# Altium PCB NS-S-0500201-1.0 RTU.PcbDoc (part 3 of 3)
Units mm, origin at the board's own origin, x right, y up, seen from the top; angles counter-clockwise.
Board outline 170 x 90 mm, 6 copper layers (TOP, L2_GND, L3_SIG, L4_VCC, L5_GND, BOT), stack 1.4 mm thick; 260 components, 230 nets, 1133 pads, 705 vias.
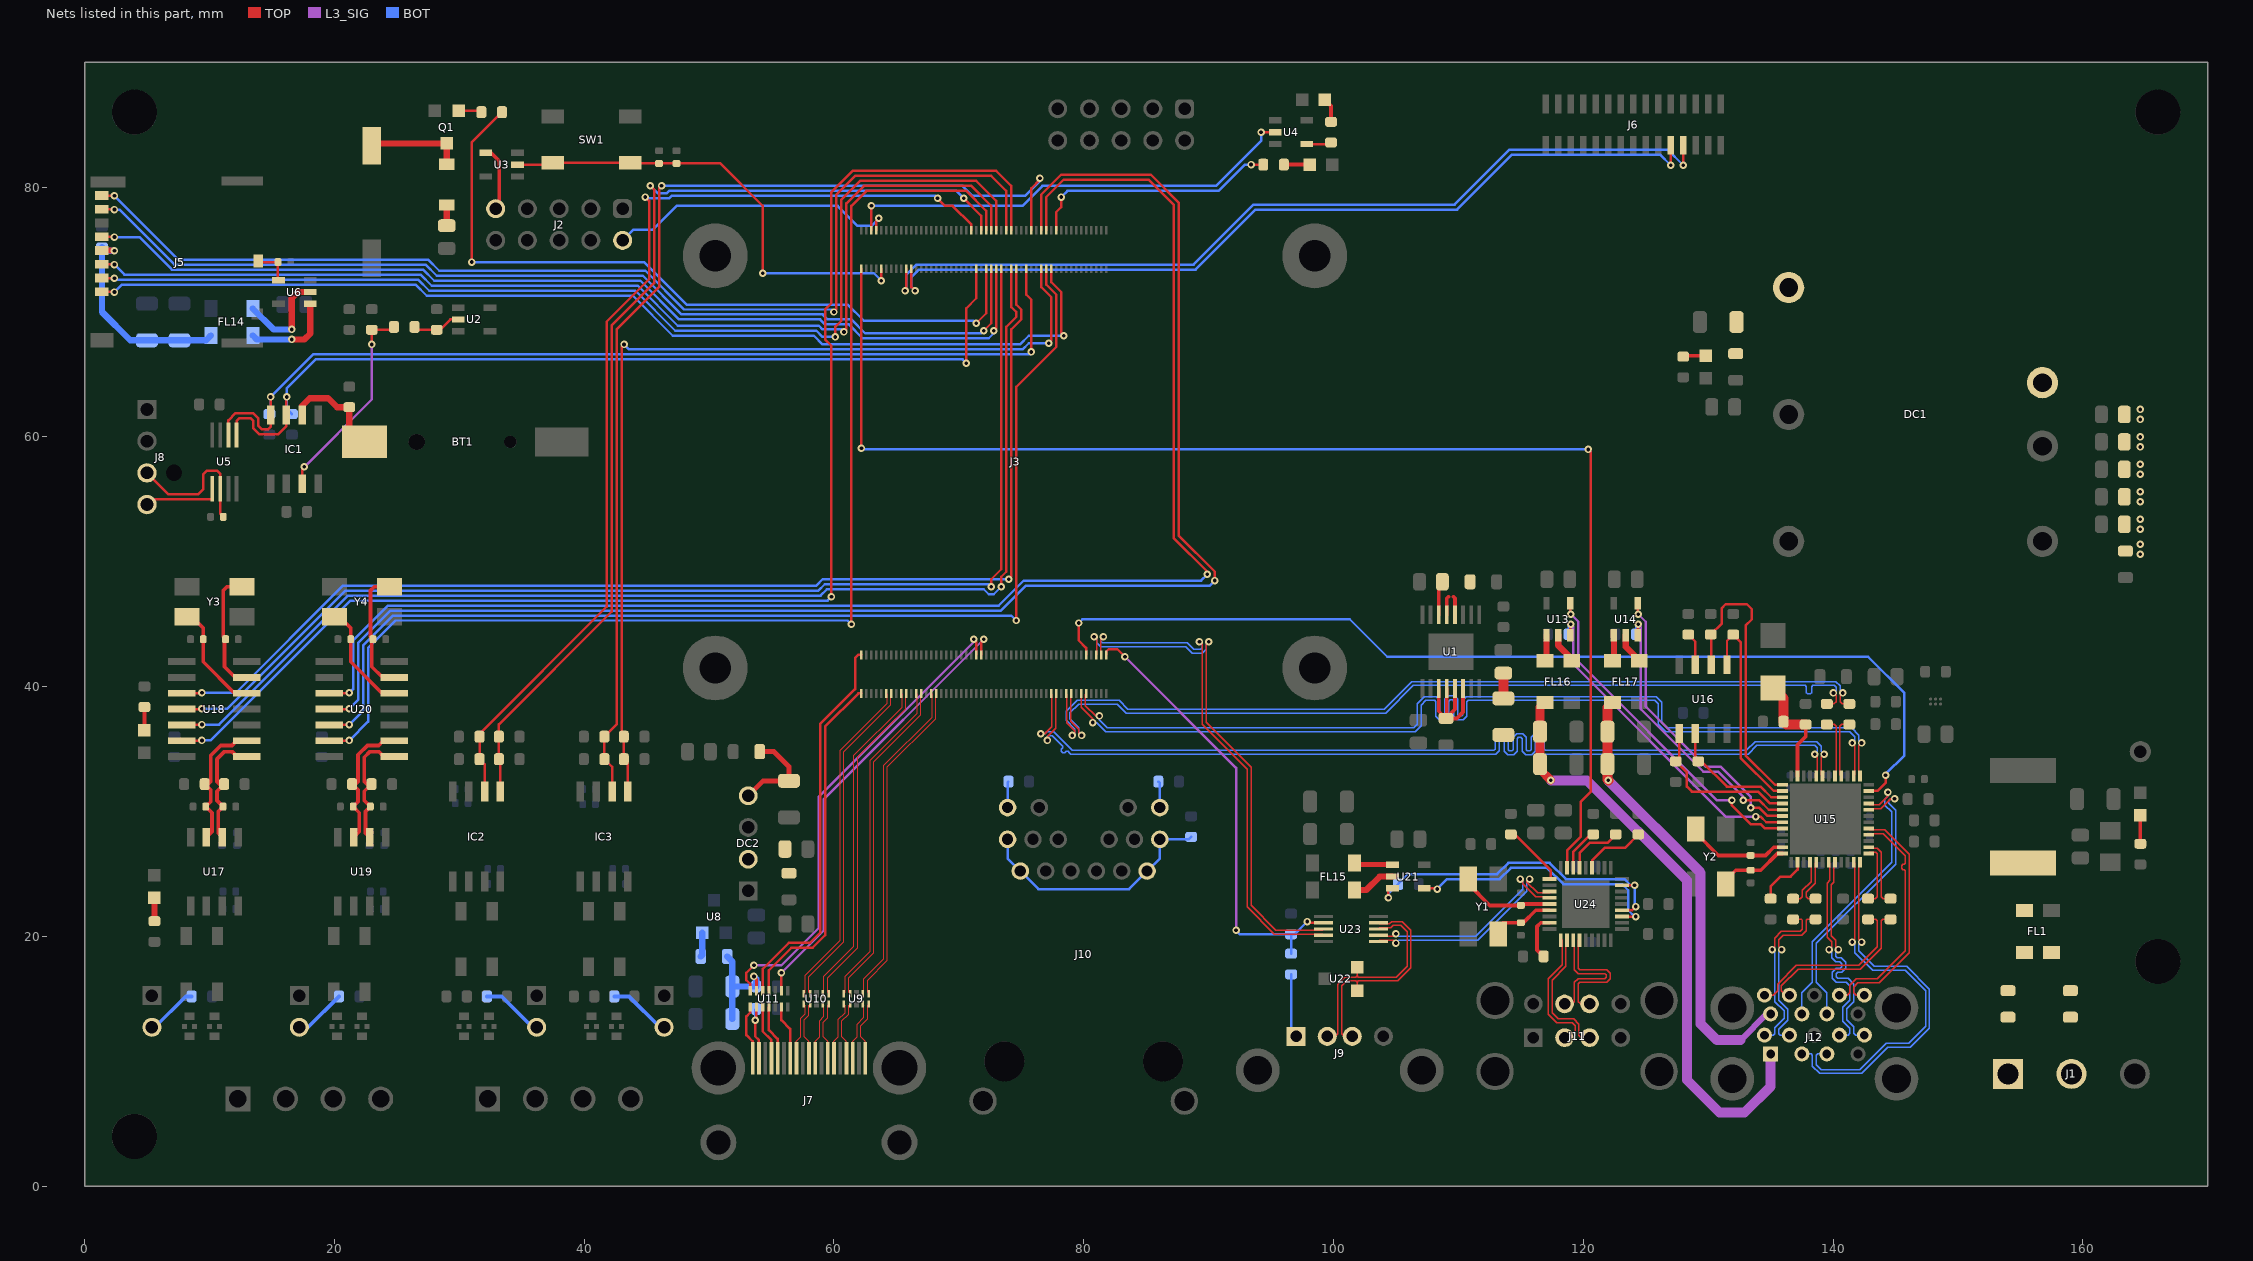
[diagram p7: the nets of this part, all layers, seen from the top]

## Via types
v1: diameter 0.6, hole 0.3, TOP to BOT, tented both sides, 705 vias

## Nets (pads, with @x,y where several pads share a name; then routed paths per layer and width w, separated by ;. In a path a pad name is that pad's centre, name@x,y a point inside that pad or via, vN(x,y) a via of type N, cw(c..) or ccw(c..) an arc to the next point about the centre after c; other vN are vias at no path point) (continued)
GPIO17: J3.50 R11.2 | length 60.1
  TOP w0.2: v1(31,74) 31,83.575 R11.2@33.425,86 ; v1(71.4,69.1) 72.2,69.9 J3.50@72.2,73.46
  BOT w0.2: v1(31,74) 44.8,74 48.2,70.6 61.1,70.6 62.4,69.3 71.2,69.3 v1(71.4,69.1)
HDMI0_CEC: J3.151 U11.9 | length 36.2
  TOP w0.2: U11.9@55.8,15.65 v1(55.8,17.1) ; J3.151@71.8,42.54 71.8,43.6 v1(72,43.8)
  L3_SIG w0.2: v1(55.8,17.1) 59.2,20.5 59.2,31 v1(72,43.8)
HDMI0_CLK1_N: J7.12 U10.1 | length 4.7
  TOP w0.09: J7.12@57,10.235 57,11.6 57.355,11.955 57.355,13.465 57.705,13.815 57.705,14.478 U10.1@57.6,14.583
HDMI0_CLK1_P: J7.10 U10.2 | length 4.7
  TOP w0.09: J7.10@58,10.235 58,11.6 57.645,11.955 57.645,13.345 57.995,13.695 57.995,14.478 U10.2@58.1,14.583
HDMI0_CLK_N: J3.190 U10.10 | length 26.8
  TOP w0.09: U10.10@57.6,15.417 57.705,15.522 57.705,16.915 60.5,19.71 60.5,34.9 64.255,38.655 64.255,39.405 J3.190@64.2,39.46
HDMI0_CLK_P: J3.188 U10.9 | length 26.8
  TOP w0.09: U10.9@58.1,15.417 57.995,15.522 57.995,16.795 60.79,19.59 60.79,34.78 64.545,38.535 64.545,39.405 J3.188@64.6,39.46
HDMI0_HOTPLUG: J3.153 U11.14 | length 38.4
  TOP w0.2: U11.14@53.3,15.65 53.3,16.2 53,16.5 53,17.1 v1(53.6,17.7) ; v1(71.2,43.8) 71.4,43.6 J3.153@71.4,42.54
  L3_SIG w0.2: v1(53.6,17.7) 55.8,17.7 58.8,20.7 58.8,31.2 71.2,43.6 v1(71.2,43.8)
HDMI0_SCL: J3.200 U11.11 | length 28
  TOP w0.2: U11.11@54.8,15.65 54.8,17.3 56.6,19.1 58.3,19.1 59.3,20.1 59.3,36.8 61.96,39.46 J3.200@62.2,39.46
HDMI0_SDA: J3.199 U11.12 | length 31.3
  TOP w0.2: U11.12@54.3,15.65 54.3,17.4 56.4,19.5 58.1,19.5 58.9,20.3 58.9,37 61.7,39.8 61.7,42.3 61.94,42.54 J3.199@62.2,42.54
HDMI0_TX0_N: J3.184 U10.7 | length 26.7
  TOP w0.09: U10.7@59.1,15.417 59.205,15.522 59.205,16.815 61.6,19.21 61.6,34.51 65.455,38.365 65.455,39.405 J3.184@65.4,39.46
HDMI0_TX0_P: J3.182 U10.6 | length 26.7
  TOP w0.09: U10.6@59.6,15.417 59.495,15.522 59.495,16.695 61.89,19.09 61.89,34.39 65.745,38.245 65.745,39.405 J3.182@65.8,39.46
HDMI0_TX01_N: J7.9 U10.4 | length 4.7
  TOP w0.09: J7.9@58.5,10.235 58.5,11.6 58.855,11.955 58.855,13.265 59.205,13.615 59.205,14.478 U10.4@59.1,14.583
HDMI0_TX1_N: J3.178 U9.10 | length 26.5
  TOP w0.09: U9.10@60.8,15.417 60.905,15.522 60.905,16.815 62.9,18.81 62.9,34.11 66.655,37.865 66.655,39.405 J3.178@66.6,39.46
HDMI0_TX01_P: J7.7 U10.5 | length 4.7
  TOP w0.09: J7.7@59.5,10.235 59.5,11.6 59.145,11.955 59.145,13.145 59.495,13.495 59.495,14.478 U10.5@59.6,14.583
HDMI0_TX1_P: J3.176 U9.9 | length 26.5
  TOP w0.09: U9.9@61.3,15.417 61.195,15.522 61.195,16.695 63.19,18.69 63.19,33.99 66.945,37.745 66.945,39.405 J3.176@67,39.46
HDMI0_TX2_N: J3.172 U9.7 | length 26.4
  TOP w0.09: U9.7@62.3,15.417 62.405,15.522 62.405,16.615 64,18.21 64,33.71 67.855,37.565 67.855,39.405 J3.172@67.8,39.46
HDMI0_TX2_P: J3.170 U9.6 | length 26.4
  TOP w0.09: U9.6@62.8,15.417 62.695,15.522 62.695,16.495 64.29,18.09 64.29,33.59 68.145,37.445 68.145,39.405 J3.170@68.2,39.46
HDMI0_TX11_N: J7.6 U9.1 | length 4.8
  TOP w0.09: J7.6@60,10.235 60,11.6 60.355,11.955 60.355,13.355 60.905,13.905 60.905,14.478 U9.1@60.8,14.583
HDMI0_TX11_P: J7.4 U9.2 | length 4.8
  TOP w0.09: J7.4@61,10.235 61,11.6 60.645,11.955 60.645,13.235 61.195,13.785 61.195,14.478 U9.2@61.3,14.583
HDMI0_TX21_N: J7.3 U9.4 | length 4.8
  TOP w0.09: J7.3@61.5,10.235 61.5,11.6 61.855,11.955 61.855,12.965 62.405,13.515 62.405,14.478 U9.4@62.3,14.583
HDMI0_TX21_P: J7.1 U9.5 | length 4.8
  TOP w0.09: J7.1@62.5,10.235 62.5,11.6 62.145,11.955 62.145,12.845 62.695,13.395 62.695,14.478 U9.5@62.8,14.583
HDMI_5V: C31.2 C32.2 C33.1 L12.2 U11.13 | length 9.2
  TOP w0.25: v1(53.6,16.8) 53.8,16.6 U11.13@53.8,15.65
  BOT w0.5: L12.2@51.463,18.4 51.865,17.997 C32.2@51.865,16 ; C31.2@51.865,13.4 C32.2@51.865,16 ; v1(53.6,16.8) 53.775,16.625 C33.1@53.775,16 C32.2@51.865,16
Net3V3_2: 3V3.2 R4.2 | length 1.9
  TOP w0.3: 3V3.2@4.8,36.5 R4.2@4.8,38.375
Net5V_2: 5V.2 R2.2 | length 1.8
  TOP w0.3: R2.2@128,66.425 128.075,66.5 5V.2@129.8,66.5
Net5V_ISO_2: 5V_ISO.2 R3.2 | length 1.9
  TOP w0.5: R3.2@5.6,21.225 5V_ISO.2@5.6,23.1
Net24V_2: 24V.2 R1.2 | length 2.3
  TOP w0.3: R1.2@164.6,27.425 24V.2@164.6,29.7
NetBT1_1: BT1.1 C21.1 IC1.6 | length 8.3
  TOP w0.5: IC1.6@17.435,61.75 17.435,62.5 18.035,63.1 19.5,63.1 20.225,62.375 C21.1@21.2,62.375 21.2,60.8 BT1.1@22.4,59.6
NetC1_1: C1.1 C2.1 C3.1 C4.1 C5.1 DC1.3 L1.2
  other v1: 164.6,50.6 164.6,51.4 164.6,52.6 164.6,53.4 164.6,54.8 164.6,55.6 164.6,57 164.6,57.8 164.6,59.2 164.6,60 164.6,61.4 164.6,62.2
NetC12_1: C12.1 L5.2 U1.12 U1.13 U1.14 | length 5.8
  TOP w0.3: U1.14@108.425,45.75 108.425,48.11 C12.1@108.715,48.4 ; U1.13@109.075,45.75 109.075,47.075 109.2,47.2 ; 109.6,47.2 109.725,47.075 U1.12@109.725,45.75
NetC14_1: C14.1 L6.1 U1.3 U1.4 U1.5 U1.6 | length 11.1
  TOP w0.3: U1.3@108.425,39.85 108.425,38.037 L6.1@109,37.462 ; U1.4@109.075,39.85 L6.1@109.075,37.537 ; U1.5@109.725,39.85 109.725,38.187 L6.1@109.075,37.537 ; U1.6@110.375,39.85 110.375,37.975 109.862,37.462 L6.1@109,37.462 ; L6.1@109,37.462 L6.1@109.075,37.537
NetC14_2: C14.2 R5.2 | length 2
  TOP w0.8: C14.2@113.6,39.065 R5.2@113.6,41.085
NetC15_1: C15.1 DC2.4 L8.1 | length 7.7
  TOP w0.4: DC2.4@53.14,31.27 54.335,32.465 C15.1@56.4,32.465 56.4,33.6 55.2,34.8 L8.1@54.063,34.8
NetC18_2: C18.2 DC2.2 L7.2
NetC23_2: C23.2 R13.1 U2.2 | length 3.9
  TOP w0.2: C23.2@26.425,68.8 26.65,68.575 R13.1@28.2,68.575 28.475,68.575 29.3,69.4 U2.2@29.93,69.4
NetC26_1: C26.1 DC1.4 L2.1
NetC34_1: C34.1 J7.18 U11.2 | length 5.2
  TOP w0.2: U11.2@53.8,14.35 53.8,13.4 v1(53.7,13.3) 53.7,12 54,11.7 J7.18@54,10.235
  BOT w0.2: v1(53.7,13.3) 53.7,14.125 C34.1@53.775,14.2
NetC43_1: C43.1 J10.1 J10.6 J10.7 J10.12 | length 19.9
  BOT w0.2: J10.12@73.905,27.78 73.905,26.26 J10.6@74.925,25.24 76.365,23.8 83.635,23.8 J10.1@85.075,25.24 86.095,26.26 J10.7@86.095,27.78 88.405,27.78 C43.1@88.6,27.975
NetC65_1: C65.1 U24.33 Y1.1 | length 5.2
  TOP w0.3: Y1.1@113.2,20.2 113.2,20.7 113.61,21.11 C65.1@115,21.11 115.21,21.11 116.2,22.1 U24.33@117.3,22.1
NetC66_1: C66.1 U24.32 Y1.3 | length 7.7
  TOP w0.3: Y1.3@110.8,24.6 110.8,24.2 112.51,22.49 C66.1@115,22.49 115.11,22.6 U24.32@117.3,22.6
NetC82_1: C82.1 D2.2 R30.2 U15.11 | length 9.3
  TOP w0.3: U15.11@137.15,32.85 137.15,35.35 137.8,36 R30.2@137.8,36.975
  TOP w0.8: D2.2@135.2,39.9 136.025,39.075 C82.1@136.025,37.2 136.25,36.975 R30.2@137.8,36.975
NetC85_1: C85.1 U15.24 Y2.1 | length 5.7
  TOP w0.3: Y2.1@131.4,24.2 131.4,24.5 132.21,25.31 C85.1@133.4,25.31 134.21,25.31 135.55,26.65 U15.24@135.95,26.65
NetC86_1: C86.1 U15.23 Y2.3 | length 8.3
  TOP w0.3: Y2.3@129,28.6 129,28.3 130.81,26.49 C86.1@133.4,26.49 134.59,26.49 135.25,27.15 U15.23@135.95,27.15
NetC93_1: C93.1 R38.2 U17.2 U18.1 | length 10.3
  TOP w0.3: U17.2@11.035,27.95 10.7,28.285 10.7,30.01 C93.1@11.09,30.4 10.6,30.89 10.6,31.625 R38.2@11.175,32.2 10.8,32.2 10.6,32.4 10.6,34.2 11.2,34.8 11.8,34.8 12.2,34.4 U18.1@13,34.4
NetC94_1: C94.1 R37.2 U17.3 U18.2 | length 11
  TOP w0.3: U17.3@9.765,27.95 10.2,28.385 10.2,29.91 C94.1@9.71,30.4 10.1,30.79 10.1,31.725 R37.2@9.625,32.2 9.9,32.2 10.1,32.4 10.1,34.5 10.9,35.3 11.8,35.3 12.17,35.67 U18.2@13,35.67
NetC95_1: C95.1 U18.6 Y3.1 | length 10
  TOP w0.3: Y3.1@12.6,48 11.4,48 11.1,47.7 11.1,43.99 C95.1@11.29,43.8 11.2,43.71 11.2,41.6 12.05,40.75 U18.6@13,40.75
NetC96_1: C96.1 U18.5 Y3.3 | length 8.9
  TOP w0.3: Y3.3@8.2,45.6 8.6,45.6 9.51,44.69 C96.1@9.51,43.8 9.51,41.99 12.02,39.48 U18.5@13,39.48
NetC98_1: C98.1 R41.2 U19.2 U20.1 | length 10.4
  TOP w0.3: U19.2@22.835,27.95 22.5,28.285 22.5,30.01 C98.1@22.89,30.4 22.4,30.89 22.4,31.625 R41.2@22.975,32.2 22.6,32.2 22.4,32.4 22.4,34.35 22.85,34.8 23.55,34.8 23.95,34.4 U20.1@24.8,34.4
NetC99_1: C99.1 R40.2 U19.3 U20.2 | length 11.1
  TOP w0.3: U19.3@21.565,27.95 22,28.385 22,29.91 C99.1@21.51,30.4 21.9,30.79 21.9,31.725 R40.2@21.425,32.2 21.7,32.2 21.9,32.4 21.9,34.55 22.65,35.3 23.55,35.3 23.92,35.67 U20.2@24.8,35.67
NetC100_1: C100.1 U20.6 Y4.1 | length 10
  TOP w0.3: Y4.1@24.4,48 23.2,48 22.9,47.7 22.9,43.99 C100.1@23.09,43.8 23,43.71 23,41.6 23.85,40.75 U20.6@24.8,40.75
NetC101_1: C101.1 U20.5 Y4.3 | length 8.9
  TOP w0.3: Y4.3@20,45.6 20.4,45.6 21.31,44.69 C101.1@21.31,43.8 21.31,41.99 23.82,39.48 U20.5@24.8,39.48
NetCPU_RUN_2: CPU_RUN.2 R14.2 | length 2.1
  TOP w0.3: R14.2@96.025,81.8 CPU_RUN.2@98.1,81.8
NetD1_1: D1.1 R7.1 | length 1.7
  TOP w0.5: R7.1@29,76.915 D1.1@29,78.565
NetD1_2: D1.2 LS1.N Q1.3 | length 7.7
  TOP w0.5: LS1.N@23,83.3 23.2,83.5 Q1.3@29,83.5 D1.2@29,81.835
NetFL1_1: FL1.1 L11.2
NetFL1_3: FL1.3 FUSE1.1
NetFL1_4: FL1.4 L10.2
NetFL14_2: FL14.2 U6.2 | length 8
  TOP w0.5: v1(16.6,68.6) 16.6,71.1 17.1,71.6 U6.2@18.07,71.6
  BOT w0.5: FL14.2@13.475,70.275 15.15,68.6 v1(16.6,68.6)
NetFL14_3: FL14.3 U6.1 | length 7.3
  TOP w0.5: v1(16.6,67.8) 17.6,67.8 18.07,68.27 U6.1@18.07,70.65
  BOT w0.5: FL14.3@13.475,68.125 13.8,67.8 v1(16.6,67.8)
NetFL15_1: FL15.1 U21.1 | length 3.1
  TOP w0.4: FL15.1@101.675,25.875 101.8,25.75 U21.1@104.73,25.75
NetFL15_4: FL15.4 U21.2 | length 3.5
  TOP w0.5: FL15.4@101.675,23.725 102.625,23.725 103.7,24.8 U21.2@104.73,24.8
NetFL16_1: FL16.1 U13.1 | length 2.1
  TOP w0.5: FL16.1@116.925,42.075 117.05,42.2 U13.1@117.05,44.13
NetFL16_4: FL16.4 U13.2 | length 2.5
  TOP w0.5: U13.2@118,44.13 118,43.3 119.075,42.225 FL16.4@119.075,42.075
NetFL17_1: FL17.1 U14.1 | length 2.1
  TOP w0.5: FL17.1@122.325,42.075 122.45,42.2 U14.1@122.45,44.13
NetFL17_4: FL17.4 U14.2 | length 2.5
  TOP w0.5: U14.2@123.4,44.13 123.4,43.2 124.475,42.125 FL17.4@124.475,42.075
NetJ1_1: J1.1 L10.1
NetJ1_2: J1.2 L11.1
NetJ2_9: J2.9 U3.4 | length 5.3
  TOP w0.3: U3.4@32.13,82.75 32.55,82.75 33.2,82.1 33.2,78.55 J2.9@32.92,78.27
NetJ5_10: J5.10 R17.2 U6.4 | length 3.1
  TOP w0.2: J5.10@13.915,74.095 14.01,74 R17.2@15.49,74 15.49,72.59 U6.4@15.53,72.55
NetJ7_13: J7.13 U11.6 | length 4.4
  TOP w0.2: U11.6@55.8,14.35 55.8,13.3 56.5,12.6 J7.13@56.5,10.235
NetJ7_15: J7.15 U11.4 | length 4.4
  TOP w0.2: U11.4@54.8,14.35 54.8,12.5 55.5,11.8 J7.15@55.5,10.235
NetJ7_16: J7.16 U11.3 | length 4.4
  TOP w0.2: U11.3@54.3,14.35 54.3,13.7 54.3,12.4 55,11.7 J7.16@55,10.235
NetJ7_19: J7.19 U11.1 | length 4.4
  TOP w0.2: U11.1@53.3,14.35 53.3,13.9 53,13.6 53,12.1 53.5,11.6 J7.19@53.5,10.235
NetJ8_3: J8.3 R16.1 U5.6 | length 11.7
  TOP w0.2: J8.3@5,57.12 6.72,55.4 9.1,55.4 9.5,55.8 9.5,57 9.8,57.3 10.6,57.3 10.875,57.025 U5.6@10.875,55.85 10.875,53.835 R16.1@11.11,53.6
NetJ8_4: J8.4 U5.5 | length 6.2
  TOP w0.2: J8.4@5,54.58 5.42,55 10.225,55 U5.5@10.225,55.85
NetJ9_1: J9.1 R54.2 | length 5.1
  BOT w0.2: R54.2@96.6,16.975 96.6,12.4 J9.1@97,12
NetJ10_13: J10.13 R21.1 | length 2.1
  BOT w0.2: R21.1@85.975,32.4 86.095,32.28 J10.13@86.095,30.32
NetJ10_16: J10.16 R22.1 | length 2.1
  BOT w0.2: J10.16@73.905,30.32 73.905,32.33 R22.1@73.975,32.4
NetJ14_2: J14.2 R39.1 | length 4.2
  BOT w0.3: J14.2@5.4,12.73 5.63,12.73 8.1,15.2 R39.1@8.575,15.2
NetJ15_2: J15.2 R42.1 | length 4.2
  BOT w0.3: J15.2@17.2,12.73 17.905,12.73 R42.1@20.375,15.2
NetJ17_2: J17.2 R47.1 | length 5
  BOT w0.3: R47.1@32.225,15.2 33.4,15.2 35.87,12.73 J17.2@36.2,12.73
NetJ18_2: J18.2 R52.1 | length 5
  BOT w0.3: R52.1@42.425,15.2 43.6,15.2 46.07,12.73 J18.2@46.4,12.73
NetL12_1: L12.1 U8.2 | length 1.9
  BOT w0.5: L12.1@49.338,18.4 49.45,18.512 U8.2@49.45,20.3
NetPWR_ON_2: PWR_ON.2 R15.2 | length 2
  TOP w0.3: PWR_ON.2@99.3,87 99.8,86.5 R15.2@99.8,85.225
NetQ1_1: Q1.1 R11.1 | length 1.9
  TOP w0.2: Q1.1@29.95,86.1 31.675,86.1 R11.1@31.775,86
NetR15_1: R15.1 U4.4 | length 2
  TOP w0.2: U4.4@97.87,83.45 99.675,83.45 R15.1@99.8,83.575
NetR31_2: R31.2 U15.26 | length 4.3
  TOP w0.2: R31.2@135,23.025 135,24 135.8,24.8 136.6,24.8 137.15,25.35 U15.26@137.15,25.95
NetR34_2: R34.2 U16.3 | length 2.7
  TOP w0.2: R34.2@128.4,44.175 128.965,43.61 U16.3@128.965,41.75
NetR56_2: R56.2 U24.24 | length 4.7
  TOP w0.2: U24.24@119.7,25.5 119.7,26.7 120.5,27.5 121.925,27.5 R56.2@122.6,28.175
NetR57_2: R57.2 U24.22 | length 5.2
  TOP w0.2: U24.22@120.7,25.5 120.7,26.1 121.7,27.1 123.325,27.1 R57.2@124.4,28.175
NetR58_2: R58.2 U24.28 | length 5.1
  TOP w0.2: R58.2@114.2,28.175 114.525,28.175 117.4,25.3 117.4,24.7 U24.28@117.3,24.6
NetR59_2: R59.2 U24.25 | length 3.5
  TOP w0.2: U24.25@119.2,25.5 119.2,26.8 120.575,28.175 R59.2@120.8,28.175
NetR60_2: R60.2 U24.35 | length 3.7
  TOP w0.3: R60.2@116.825,18.4 116.3,18.925 116.3,20.8 116.6,21.1 U24.35@117.3,21.1
nEXTRST: J3.100 U24.26 | length 107
  TOP w0.2: v1(62.2,59.1) J3.100@62.2,73.46 ; U24.26@118.7,25.5 118.7,26.9 119.8,28 119.8,30.8 120.6,31.6 120.6,58.8 v1(120.4,59)
  BOT w0.2: v1(62.2,59.1) 62.3,59 v1(120.4,59)
nRPIBOOT: J2.2 J3.93 | length 23.6
  TOP w0.2: J3.93@63.4,76.54 63.4,77.3 v1(63.6,77.5)
  BOT w0.2: J2.2@43.08,75.73 43.95,76.6 45.5,76.6 47.4,78.5 60.3,78.5 61.9,76.9 63,76.9 v1(63.6,77.5)
nRTC_INT: C23.1 IC1.3 R12.1 | length 16.5
  TOP w0.2: IC1.3@17.435,56.25 17.435,57.435 v1(17.6,57.6) ; v1(23,67.4) R12.1@23,68.575 24.55,68.575 C23.1@24.775,68.8
  L3_SIG w0.2: v1(17.6,57.6) 23,63 v1(23,67.4)
nUSB_OC: R53.2 U21.3 U24.13 U24.17 | length 26.9
  TOP w0.2: v1(104.4,23.1) 104.4,23.8 104.45,23.85 U21.3@104.73,23.85 ; U24.17@123,24.1 v1(124.1,24.1) ; U24.13@123.1,22.1 123.9,22.1 v1(124.2,22.4)
  BOT w0.2: v1(104.4,23.1) 104.4,23.425 105.975,25 113.1,25 114,25.9 117.3,25.9 118.6,24.6 123.3,24.6 123.8,24.1 v1(124.1,24.1) 124.1,22.5 v1(124.2,22.4)
OCI1B: R28.2 U13.3 U15.19 | length 27
  TOP w0.2: U13.3@118.95,44.13 118.95,44.95 v1(119,45) ; v1(133.8,29.6) 134.2,29.6 134.65,29.15 U15.19@135.95,29.15
  L3_SIG w0.2: v1(119,45) 119.2,44.8 119.2,41.8 131.4,29.6 v1(133.8,29.6)
  BOT w0.2: R28.2@118.825,44.2 118.825,44.825 v1(119,45)
OCI2B: R29.2 U14.3 U15.17 | length 23.5
  TOP w0.2: U14.3@124.35,44.13 124.35,44.95 v1(124.4,45) ; v1(132.8,30.9) 134.1,30.9 134.85,30.15 U15.17@135.95,30.15
  L3_SIG w0.2: v1(124.4,45) 124.6,44.8 124.6,38.2 129.6,33.2 130.8,33.2 132.8,31.2 v1(132.8,30.9)
  BOT w0.2: R29.2@124.225,44.2 124.225,44.825 v1(124.4,45)
PCIe_CLK_N: J3.112 U15.2 | length 76.9
  TOP w0.11: J3.112@79.8,39.46 79.8,38.362 80.725,37.436 v1(80.725,37.125) ; v1(141.525,35.5) 141.745,35.28 141.745,32.945 U15.2@141.65,32.85
  BOT w0.11: v1(80.725,37.125) 81.036,37.125 81.762,36.4 106.538,36.4 107.01,36.872 107.01,38.51 107.4,38.9 107.7,38.9 108.096,38.9 108.199,38.798 108.199,37.645 108.483,37.361 108.944,37.361 109.228,37.645 109.228,38.85 109.331,38.953 109.536,38.953 109.638,38.85 109.638,37.644 109.923,37.36 110.384,37.36 110.668,37.644 110.668,38.798 110.771,38.9 110.917,38.9 125.727,38.9 125.99,38.637 125.99,37.008 126.598,36.4 141.345,36.4 141.745,36 141.745,35.72 v1(141.525,35.5)
PCIe_CLK_P: J3.110 U15.1 | length 77
  TOP w0.11: J3.110@80.2,39.46 80.11,39.37 80.11,38.49 80.944,37.656 v1(81.256,37.656) ; U15.1@142.15,32.85 142.055,32.945 142.055,35.28 v1(142.275,35.5)
  BOT w0.11: v1(81.256,37.656) 81.256,37.344 81.89,36.71 106.41,36.71 106.7,37 106.7,38.638 107.272,39.21 107.7,39.21 108.224,39.21 108.509,38.926 108.509,37.774 108.611,37.671 108.816,37.671 108.918,37.774 108.918,38.979 109.203,39.263 109.664,39.263 109.948,38.979 109.948,37.773 110.051,37.67 110.256,37.67 110.358,37.773 110.358,38.926 110.643,39.21 110.917,39.21 125.855,39.21 126.3,38.765 126.3,37.137 126.727,36.71 141.473,36.71 142.055,36.128 142.055,35.72 v1(142.275,35.5)
PCIe_nRST: J3.109 U15.47 | length 80.9
  TOP w0.2: v1(79.6,45.1) 79.6,43.7 80.2,43.1 J3.109@80.2,42.54 ; U15.47@142.85,31.65 143.55,31.65 144.2,32.3 v1(144.2,32.9)
  BOT w0.2: v1(79.6,45.1) 79.9,45.4 101.3,45.4 104.3,42.4 142.8,42.4 145.7,39.5 145.7,34.5 144.2,33 v1(144.2,32.9)
PCIe_RX1_N: C78.2 U15.4 | length 4.8
  TOP w0.11: U15.4@140.65,32.85 140.55,32.95 140.55,36.845 140.68,36.975 C78.2@141.3,36.975
PCIe_RX1_P: C80.2 U15.5 | length 4.8
  TOP w0.11: C80.2@139.5,36.975 140.1,36.975 140.24,36.835 140.24,32.94 U15.5@140.15,32.85
PCIe_RX_N: C78.1 J3.118 | length 72
  TOP w0.11: J3.118@78.6,39.46 78.645,39.415 78.645,37.117 79.3,36.462 79.3,36.3 79.1,36.1 v1(79.08,36.1) ; v1(140.775,39.5) 140.555,39.28 140.555,38.8 140.73,38.625 C78.1@141.3,38.625
  BOT w0.11: v1(79.08,36.1) 79.3,36.32 79.3,36.6 78.59,37.31 78.59,38.028 79.472,38.91 82.828,38.91 83.538,38.2 104.062,38.2 106.272,40.41 140.228,40.41 140.555,40.083 140.555,39.72 v1(140.775,39.5)
PCIe_RX_P: C80.1 J3.116 | length 72.1
  TOP w0.11: J3.116@79,39.46 78.955,39.415 78.955,37.245 79.61,36.59 79.61,36.3 79.81,36.1 v1(79.83,36.1) ; C80.1@139.5,38.625 140.07,38.625 140.245,38.8 140.245,39.28 v1(140.025,39.5)
  BOT w0.11: v1(79.83,36.1) 79.61,36.32 79.61,36.728 78.9,37.438 78.9,37.9 79.6,38.6 82.7,38.6 83.41,37.89 104.19,37.89 106.4,40.1 137.3,40.1 137.765,40.1 137.868,39.998 137.868,39.52 137.97,39.418 138.175,39.418 138.278,39.52 138.278,39.998 138.38,40.1 138.5,40.1 140.1,40.1 140.245,39.955 140.245,39.72 v1(140.025,39.5)
PCIe_TX_N: J3.124 U15.7 | length 76.9
  TOP w0.11: v1(76.57,36.23) 76.881,36.23 77.445,36.795 77.445,39.415 J3.124@77.4,39.46 ; U15.7@139.15,32.85 139.055,32.945 139.055,34.38 v1(139.275,34.6)
  BOT w0.11: v1(76.57,36.23) 76.881,36.23 77.05,36.4 77.6,36.4 79.1,34.9 112.7,34.9 112.846,34.9 112.948,35.002 112.948,35.964 113.232,36.248 113.694,36.248 113.978,35.964 113.978,34.967 114.081,34.864 114.286,34.864 114.388,34.967 114.388,35.964 114.672,36.248 115.134,36.248 115.418,35.964 115.418,34.967 115.521,34.864 115.726,34.864 115.828,34.967 115.828,35.964 116.112,36.248 116.574,36.248 116.858,35.964 116.858,35.002 116.961,34.9 117.203,34.9 133.062,34.9 133.772,35.61 138.673,35.61 139.055,35.228 139.055,34.82 v1(139.275,34.6)
PCIe_TX_P: J3.122 U15.8 | length 76.9
  TOP w0.11: v1(77.1,35.7) 77.1,36.011 77.755,36.666 77.755,39.415 J3.122@77.8,39.46 ; v1(138.525,34.6) 138.745,34.38 138.745,32.945 U15.8@138.65,32.85
  BOT w0.11: v1(77.1,35.7) 77.1,36.011 77.179,36.09 77.472,36.09 77.981,35.58 78.02,35.542 78.31,35.252 78.31,35.107 78.187,34.984 78.187,34.839 78.332,34.694 78.477,34.694 78.6,34.817 78.745,34.817 78.832,34.729 78.871,34.69 78.972,34.59 112.7,34.59 112.974,34.59 113.258,34.874 113.258,35.836 113.361,35.938 113.566,35.938 113.668,35.836 113.668,34.838 113.952,34.554 114.414,34.554 114.698,34.838 114.698,35.836 114.801,35.938 115.006,35.938 115.108,35.836 115.108,34.838 115.392,34.554 115.854,34.554 116.138,34.838 116.138,35.836 116.241,35.938 116.446,35.938 116.548,35.836 116.548,34.874 116.832,34.59 117.203,34.59 133.19,34.59 133.9,35.3 138.545,35.3 138.745,35.1 138.745,34.82 v1(138.525,34.6)
PI_LED_nPWR: J3.95 U4.2 | length 37.1
  TOP w0.2: J3.95@63,76.54 v1(63,78.5) ; v1(94.2,84.4) U4.2@95.33,84.4
  BOT w0.2: v1(63,78.5) 75.1,78.5 76.7,80.1 90.6,80.1 94.2,83.7 v1(94.2,84.4)
Pi_nLED_Activity: J3.21 R14.1 | length 20.1
  TOP w0.2: J3.21@77.8,76.54 77.8,78 78.2,78.4 v1(78.2,79.2) ; v1(93.4,81.8) R14.1@94.375,81.8
  BOT w0.2: v1(78.2,79.2) 78.7,79.7 90.8,79.7 92.9,81.8 v1(93.4,81.8)
PPON1: U13.4 U15.20 | length 27.1
  TOP w0.2: U13.4@118.95,46.67 118.95,45.85 v1(119,45.8) ; v1(131.9,30.9) 131.9,30.5 133.4,29 134.2,29 134.55,28.65 U15.20@135.95,28.65
  L3_SIG w0.2: v1(119,45.8) 119.6,45.2 119.6,42 130.7,30.9 v1(131.9,30.9)
PPON2: U14.4 U15.18 | length 23.6
  TOP w0.2: U14.4@124.35,46.67 124.35,45.85 v1(124.4,45.8) ; v1(133.4,30.3) 134.1,30.3 134.75,29.65 U15.18@135.95,29.65
  L3_SIG w0.2: v1(124.4,45.8) 125,45.2 125,38.4 129.8,33.6 131,33.6 133.4,31.2 v1(133.4,30.3)
RUN_PG: C19.1 J3.92 R10.1 SW1.3 SW1.4 U3.2 | length 37.2
  TOP w0.2: U3.2@34.67,81.8 37.35,81.8 SW1.3@37.5,81.95 SW1.4@43.7,81.95 43.76,81.89 C19.1@46,81.89 R10.1@47.4,81.89 50.91,81.89 54.3,78.5 v1(54.3,73.1) ; v1(63.8,72.5) J3.92@63.8,73.46
  BOT w0.2: v1(54.3,73.1) 63.2,73.1 v1(63.8,72.5)
RXD0: C110.1 IC2.1 J3.51 R45.1 | length 82.6
  TOP w0.2: IC2.1@33.305,31.6 33.305,34.07 C110.1@33.175,34.2 R45.1@33.175,36 33.175,36.975 42.2,46 42.2,68.914 45.6,72.314 45.6,79.8 v1(45.3,80.1) ; v1(70.4,79.1) 71.8,77.7 J3.51@71.8,76.54
  BOT w0.2: v1(45.3,80.1) 45.9,79.5 46.6,79.5 46.8,79.7 69.8,79.7 v1(70.4,79.1)
RXD5: C116.1 IC3.1 J3.28 R50.1 | length 76.8
  TOP w0.2: v1(43.2,67.4) 43,67.2 43,36.175 R50.1@43.175,36 C116.1@43.175,34.2 43.505,33.87 IC3.1@43.505,31.6 ; J3.28@76.6,73.46 76.6,72 77.4,71.2 77.4,67.7 v1(77.2,67.5)
  BOT w0.2: v1(43.2,67.4) 43.6,67 75.1,67 75.6,67.5 v1(77.2,67.5)
SCL0: J3.80 J6.11 | length 69.9
  TOP w0.2: J3.80@66.2,73.46 66.2,72 v1(66.5,71.7) ; v1(127,81.75) J6.11@127,83.35
  BOT w0.2: v1(66.5,71.7) 66.2,72 66.2,72.8 66.8,73.4 88.966,73.4 93.766,78.2 109.9,78.2 114.3,82.6 126.15,82.6 v1(127,81.75)
SCL3: IC1.8 J3.34 R8.1 U5.2 | length 78.9
  TOP w0.2: U5.2@11.525,60.15 11.525,61.325 12.1,61.9 13.5,61.9 13.9,61.5 13.9,60.9 14.2,60.6 14.7,60.6 14.895,60.795 IC1.8@14.895,61.75 14.895,63.195 v1(14.9,63.2) ; J3.34@75.4,73.46 75.4,71.4 75.8,71 v1(75.8,66.8)
  BOT w0.2: R8.1@14.8,61.825 14.9,61.925 v1(14.9,63.2) 18.3,66.6 75.7,66.6 75.8,66.7 v1(75.8,66.8)
SD1_CLK: J3.46 J5.5 | length 80.2
  TOP w0.2: J5.5@1.375,76.02 2.38,76.02 v1(2.4,76) ; v1(72.8,68.5) 73,68.7 J3.46@73,73.46
  BOT w0.2: v1(2.4,76) 4.4,76 7,73.4 27.1,73.4 28,72.5 44.5,72.5 47.6,69.4 58.9,69.4 59.3,69 61.2,69 62.3,67.9 72.4,67.9 72.8,68.3 v1(72.8,68.5)
SD1_CMD: J3.47 J5.3 | length 86.9
  TOP w0.2: J5.3@1.375,73.82 2.38,73.82 v1(2.4,73.8) ; v1(60.8,68.4) 61,68.6 61,78.7 62.4,80.1 71,80.1 72.6,78.5 J3.47@72.6,76.54
  BOT w0.2: v1(2.4,73.8) 3.2,73 26.9,73 27.8,72.1 44.3,72.1 47.5,68.9 58.8,68.9 59.1,68.6 60.6,68.6 v1(60.8,68.4)
SD1_DAT0: J3.48 J5.7 | length 80
  TOP w0.2: J5.7@1.375,78.22 2.38,78.22 v1(2.4,78.2) ; v1(72,68.5) 72.6,69.1 J3.48@72.6,73.46
  BOT w0.2: v1(2.4,78.2) 2.8,78.2 7.2,73.8 27.3,73.8 28.2,72.9 44.7,72.9 47.8,69.8 59.1,69.8 59.5,69.4 61.4,69.4 62.5,68.3 71.8,68.3 v1(72,68.5)
SD1_DAT1: J3.41 J5.8 | length 89.8
  TOP w0.2: J5.8@1.375,79.32 2.38,79.32 v1(2.4,79.3) ; v1(60,70) 60.2,70.2 60.2,79.4 61.7,80.9 72.6,80.9 73.8,79.7 J3.41@73.8,76.54
  BOT w0.2: v1(2.4,79.3) 7.5,74.2 27.5,74.2 28.4,73.3 44.9,73.3 48,70.2 59.8,70.2 v1(60,70)
SD1_DAT2: J3.24 J5.1 | length 85.3
  TOP w0.2: J5.1@1.375,71.62 2.38,71.62 v1(2.4,71.6) ; J3.24@77.4,73.46 77.4,72.4 78.2,71.6 78.2,68.3 v1(78.4,68.1)
  BOT w0.2: v1(2.4,71.6) 3,72.2 26.5,72.2 27.4,71.3 43.9,71.3 47.1,68.1 58.4,68.1 59.1,67.4 74.9,67.4 75.6,68.1 v1(78.4,68.1)
SD1_DAT3: J3.45 J5.2 | length 88
  TOP w0.2: J5.2@1.375,72.72 2.38,72.72 v1(2.4,72.7) ; v1(60.1,68) 60.1,68.8 60.6,69.3 60.6,79 62.1,80.5 71.4,80.5 73,78.9 J3.45@73,76.54
  BOT w0.2: v1@2.429,72.7 v1(2.4,72.7) 2.5,72.6 26.7,72.6 27.6,71.7 44.1,71.7 47.3,68.5 58.6,68.5 59.1,68 v1(60.1,68)
SD_PWR: C24.1 C27.2 C28.2 FL14.4 J5.4 | length 17.1
  TOP w0.5: J5.4@1.375,74.92 2.38,74.92 v1(2.4,74.9)
  BOT w0.5: v1(2.4,74.9) 1.675,74.9 C24.1@1.4,75.175 1.4,70 3.665,67.735 C28.2@5,67.735 C27.2@7.6,67.735 9.735,67.735 FL14.4@10.125,68.125
SDA0: J3.82 J6.12 | length 71.6
  TOP w0.2: v1(65.7,71.7) 65.8,71.8 J3.82@65.8,73.46 ; v1(128,81.75) J6.12@128,83.35
  BOT w0.2: v1(65.7,71.7) 65.8,71.8 65.8,73 66.6,73.8 88.8,73.8 93.6,78.6 109.7,78.6 114.1,83 126.75,83 v1(128,81.75)
SDA3: IC1.7 J3.54 R9.1 U5.1 | length 74.3
  TOP w0.2: U5.1@12.175,60.15 12.175,61.275 12.4,61.5 13.3,61.5 13.5,61.3 13.5,60.7 14,60.2 15.5,60.2 16.165,60.865 IC1.7@16.165,61.75 16.165,63.165 v1(16.2,63.2) ; v1(70.6,65.9) 70.6,70.3 71.4,71.1 J3.54@71.4,73.46
  BOT w0.2: R9.1@16.6,61.825 16.2,62.225 v1(16.2,63.2) 16.2,63.9 18.5,66.2 70.3,66.2 v1(70.6,65.9)
SPI0_CE0_N: J3.39 U18.13 | length 108.8
  TOP w0.2: U18.13@7.8,35.67 9.37,35.67 v1(9.4,35.7) ; v1(59.8,47.2) 59.8,67.3 59.3,67.8 59.3,70.2 59.8,70.7 59.8,79.6 61.5,81.3 73,81.3 74.2,80.1 J3.39@74.2,76.54
  BOT w0.2: v1(9.4,35.7) 10.1,35.7 21.3,46.9 59.5,46.9 v1(59.8,47.2)
SPI0_MISO: J3.40 U18.12 | length 96.6
  TOP w0.2: U18.12@7.8,36.94 9.37,36.94 v1(9.4,36.97) ; v1(73.4,48) 73.4,48.8 73.8,49.2 73.8,68.8 74.6,69.6 74.6,70 74.2,70.4 J3.40@74.2,73.46
  BOT w0.2: v1(9.4,36.97) 10.77,36.97 21.1,47.3 58.931,47.3 59.431,47.8 72,47.8 72.4,47.4 72.8,47.4 v1(73.4,48)
SPI0_MOSI: J3.44 U18.11 | length 94.8
  TOP w0.2: U18.11@7.8,38.21 9.37,38.21 v1(9.4,38.24) ; v1(72.6,48) 72.6,48.6 73.4,49.4 J3.44@73.4,73.46
  BOT w0.2: v1(9.4,38.24) 11.44,38.24 20.9,47.7 58.766,47.7 59.266,48.2 72.4,48.2 v1(72.6,48)
SPI0_SCLK: J3.38 U18.10 | length 95.4
  TOP w0.2: U18.10@7.8,39.48 9.37,39.48 v1(9.4,39.51) ; v1(74,48.6) 74.2,48.8 74.2,68.6 75,69.4 75,70.2 74.6,70.6 J3.38@74.6,73.46
  BOT w0.2: v1(9.4,39.51) 12.11,39.51 20.7,48.1 58.6,48.1 59.1,48.6 v1(74,48.6)
SPI6_CE0_N: J3.49 U20.13 | length 96.4
  TOP w0.2: U20.13@19.6,35.67 21.17,35.67 v1(21.2,35.7) ; v1(61.4,45) 61.4,78.5 62.6,79.7 70.6,79.7 72.2,78.1 J3.49@72.2,76.54
  BOT w0.2: v1(21.2,35.7) 22.7,37.2 22.7,43.1 24.9,45.3 61.1,45.3 v1(61.4,45)
SPI6_MISO: J3.26 U20.12 | length 91.7
  TOP w0.2: U20.12@19.6,36.94 21.17,36.94 v1(21.2,36.97) ; v1(74.6,45.3) 74.6,64 77.8,67.2 77.8,71.4 77,72.2 J3.26@77,73.46
  BOT w0.2: v1(21.2,36.97) 22.3,38.07 22.3,43.3 24.7,45.7 74.2,45.7 v1(74.6,45.3)
SPI6_MOSI: J3.27 U20.11 | length 124.7
  TOP w0.2: U20.11@19.6,38.21 21.17,38.21 v1(21.2,38.24) ; J3.27@76.6,76.54 76.6,79.4 78.2,81 85.366,81 87.6,78.766 87.6,52.1 90.5,49.2 v1(90.5,48.5)
  BOT w0.2: v1(21.2,38.24) 21.9,38.94 21.9,43.5 24.5,46.1 73.366,46.1 75.366,48.1 90.1,48.1 v1(90.5,48.5)
SPI6_SCLK: J3.25 U20.10 | length 121.6
  TOP w0.2: U20.10@19.6,39.48 21.17,39.48 v1(21.2,39.51) ; J3.25@77,76.54 77,79.2 78.4,80.6 85.2,80.6 87.2,78.6 87.2,51.9 89.9,49.2 v1(89.9,49)
  L3_SIG w0.2: v1(89.9,49) v1@90,49
  BOT w0.2: v1(21.2,39.51) 21.5,39.81 21.5,43.7 24.3,46.5 73.2,46.5 75.2,48.5 89.4,48.5 v1(89.9,49)
SPICSB: R32.2 U15.14 U16.1 | length 17.2
  TOP w0.2: U16.1@131.505,41.75 131.505,43.68 R32.2@132,44.175 132.6,43.575 132.6,34.3 135.25,31.65 U15.14@135.95,31.65
SPISCK: R36.2 U15.15 U16.6 | length 10.3
  TOP w0.2: U16.6@128.965,36.25 128.965,34.26 R36.2@129.2,34.025 129.475,34.025 131.5,32 134.2,32 135.05,31.15 U15.15@135.95,31.15
SPISI: R35.2 U15.16 U16.5 | length 13
  TOP w0.2: U16.5@127.695,36.25 127.695,34.32 R35.2@127.4,34.025 128.3,33.125 128.3,32 128.7,31.6 134,31.6 134.95,30.65 U15.16@135.95,30.65
SPISO: R33.2 U15.13 U16.2 | length 23.5
  TOP w0.2: U16.2@130.235,41.75 130.235,44.14 R33.2@130.2,44.175 131.1,45.075 131.1,46.3 131.4,46.6 133.1,46.6 133.5,46.2 133.5,45.4 133,44.9 133,34.5 135.35,32.15 U15.13@135.95,32.15
TXD0: C111.1 IC2.2 J3.55 R44.2 | length 81.2
  TOP w0.2: IC2.2@32.035,31.6 32.035,33.79 C111.1@31.625,34.2 R44.2@31.625,36 31.625,36.225 41.8,46.4 41.8,69.221 45.2,72.621 45.2,78.9 v1(44.9,79.2) ; v1(68.3,79.1) 68.9,78.5 69.5,78.5 71,77 J3.55@71,76.54
  BOT w0.2: v1(44.9,79.2) 45,79.1 46.8,79.1 47,79.3 68.1,79.3 v1(68.3,79.1)
TXD5: C117.1 IC3.2 J3.31 R49.2 | length 86.4
  TOP w0.2: IC3.2@42.235,31.6 42.235,33.59 C117.1@41.625,34.2 R49.2@41.625,36 42.6,36.975 42.6,68.607 46,72.007 46,79.9 v1(46.2,80.1) ; J3.31@75.8,76.54 75.8,79.9 76.5,80.6 v1(76.5,80.7)
  BOT w0.2: v1(46.2,80.1) 70.3,80.1 71.1,79.3 75.3,79.3 76.5,80.5 v1(76.5,80.7)
U2D1_N: J12.2 U15.36 | length 30.2
  TOP w0.11: U15.36@142.15,25.95 142.055,25.855 142.055,19.77 v1(142.275,19.55)
  BOT w0.11: J12.2@137.5,10.6 138.245,10.6 138.345,10.5 138.345,9.617 138.922,9.04 142.278,9.04 144.388,11.15 146.188,11.15 147.71,12.672 147.71,15.79 145.89,17.61 143.29,17.61 142.055,18.845 142.055,19.33 v1(142.275,19.55)
U2D1_P: J12.3 U15.35 | length 29.2
  TOP w0.11: v1(141.525,19.55) 141.745,19.77 141.745,25.855 U15.35@141.65,25.95
  BOT w0.11: J12.3@139.5,10.6 138.755,10.6 138.655,10.5 138.655,9.745 139.05,9.35 142.15,9.35 144.26,11.46 146.06,11.46 147.4,12.8 147.4,15.662 145.762,17.3 143.162,17.3 141.745,18.717 141.745,19.33 v1(141.525,19.55)
U2D2_N: J12.11 U15.45 | length 23.2
  TOP w0.11: U15.45@142.85,30.65 142.945,30.555 143.705,30.555 144.394,31.244 v1(144.394,31.556)
  BOT w0.11: J12.11@137.5,13.8 137.5,15.5 138.345,16.345 138.345,19.583 144.69,25.928 144.69,29.972 144.14,30.522 144.14,30.99 144.394,31.244 v1(144.394,31.556)
U2D2_P: J12.12 U15.44 | length 23.2
  TOP w0.11: U15.44@142.85,30.15 142.945,30.245 143.833,30.245 144.614,31.025 v1(144.925,31.025)
  BOT w0.11: J12.12@139.5,13.8 139.5,15.49 138.655,16.335 138.655,19.455 145,25.8 145,30.1 144.45,30.65 144.45,30.862 144.614,31.025 v1(144.925,31.025)
U3RXD1_N: J12.5 U15.32 | length 17.6
  TOP w0.11: U15.32@140.15,25.95 140.055,25.855 140.055,24.355 139.85,24.15 139.85,20.05 140.21,19.69 140.21,19.17 v1(140.43,18.95)
  BOT w0.11: v1(140.43,18.95) 140.21,18.73 140.21,18.428 140.338,18.3 140.65,18.3 141,17.95 141,17.45 140.69,17.14 140.378,17.14 140.26,17.022 140.26,16.778 140.388,16.65 141.2,16.65 141.66,16.19 141.66,14.76 141.1,14.2 141.1,13.338 141.655,12.783 141.655,12.25 141.805,12.1 J12.5@142.5,12.1
U3RXD1_P: J12.6 U15.31 | length 17.6
  TOP w0.11: U15.31@139.65,25.95 139.745,25.855 139.745,24.483 139.54,24.278 139.54,19.922 139.9,19.562 139.9,19.17 v1(139.68,18.95)
  BOT w0.11: v1(139.68,18.95) 139.9,18.73 139.9,18.3 140.21,17.99 140.522,17.99 140.69,17.822 140.69,17.578 140.562,17.45 140.25,17.45 139.95,17.15 139.95,16.65 140.26,16.34 141.072,16.34 141.35,16.062 141.35,14.888 140.79,14.328 140.79,13.21 141.345,12.655 141.345,12.25 141.195,12.1 J12.6@140.5,12.1
U3RXD2_N: J12.14 U15.41 | length 19
  TOP w0.11: J12.14@142.5,15.3 141.855,15.3 141.655,15.5 141.655,15.955 141.99,16.29 143.678,16.29 146.1,18.712 146.1,26.6 144.145,28.555 142.945,28.555 U15.41@142.85,28.65
U3RXD2_P: J12.15 U15.40 | length 18.8
  TOP w0.11: J12.15@140.5,15.3 141.145,15.3 141.345,15.5 141.345,16.083 141.862,16.6 143.55,16.6 145.79,18.84 145.79,25.2 145.79,25.255 145.688,25.358 145.58,25.358 145.477,25.46 145.477,25.665 145.58,25.768 145.688,25.768 145.79,25.87 145.79,26 145.79,26.472 144.017,28.245 142.945,28.245 U15.40@142.85,28.15
U3TXD1_1_N: C79.2 J12.8 | length 13.3
  TOP w0.11: v1(135.87,18.95) 135.65,19.17 135.65,19.75 135.99,20.09 137.49,20.09 137.855,20.455 137.855,21.3 137.93,21.375 C79.2@138.6,21.375
  BOT w0.11: v1(135.87,18.95) 135.65,18.73 135.65,14.9 136.385,14.165 136.385,13.31 135.655,12.58 135.655,12.225 135.78,12.1 J12.8@136.5,12.1
U3TXD1_1_P: C81.2 J12.9 | length 13.3
  TOP w0.11: v1(135.12,18.95) 135.34,19.17 135.34,19.878 135.862,20.4 137.362,20.4 137.545,20.583 137.545,21.3 137.47,21.375 C81.2@136.8,21.375
  BOT w0.11: J12.9@134.5,12.1 135.22,12.1 135.345,12.225 135.345,12.708 136.075,13.438 136.075,14.037 135.34,14.772 135.34,18.73 v1(135.12,18.95)
U3TXD1_N: C79.1 U15.29 | length 3.9
  TOP w0.11: C79.1@138.6,23.025 138.03,23.025 137.855,23.2 137.855,23.555 138.555,24.255 138.555,25.855 U15.29@138.65,25.95
U3TXD1_P: C81.1 U15.28 | length 3.9
  TOP w0.11: C81.1@136.8,23.025 137.37,23.025 137.545,23.2 137.545,23.683 138.245,24.383 138.245,25.855 U15.28@138.15,25.95
U3TXD2_1_N: C83.2 J12.17 | length 13.4
  TOP w0.11: J12.17@136.5,15.3 136.2,15.3 135.86,15.64 135.86,16.06 137.19,17.39 142.19,17.39 143.855,19.055 143.855,21.25 143.98,21.375 C83.2@144.6,21.375
U3TXD2_1_P: C84.2 J12.18 | length 13.8
  TOP w0.11: J12.18@134.5,15.3 135.195,15.3 135.55,15.655 135.55,16.188 137.062,17.7 142.062,17.7 143.545,19.183 143.545,21.25 143.42,21.375 C84.2@142.8,21.375
U3TXD2_N: C83.1 U15.38 | length 5.5
  TOP w0.11: U15.38@142.85,27.15 142.945,27.055 143.533,27.055 143.855,26.733 143.855,23.905 143.855,23.2 144.03,23.025 C83.1@144.6,23.025
U3TXD2_P: C84.1 U15.37 | length 5
  TOP w0.11: C84.1@142.8,23.025 143.37,23.025 143.545,23.2 143.545,24.033 143.545,26.605 143.405,26.745 142.945,26.745 U15.37@142.85,26.65
USB3CH1: C71.2 C72.2 FL16.2 J12.1 | length 48.2
  TOP w0.7: FL16.2@116.925,38.725 116.535,38.335 C71.2@116.535,36.4 C72.2@116.535,33.8 116.535,33.365 v1(117.4,32.5)
  L3_SIG w0.8: v1(117.4,32.5) 120.3,32.5 128.3,24.5 128.3,8.5 130.9,5.9 132.9,5.9 135,8 J12.1@135,10.6
USB3CH2: C73.2 C74.2 FL17.2 J12.10 | length 36
  TOP w0.8: v1(122,32.5) 121.935,32.565 C74.2@121.935,33.8 C73.2@121.935,36.4 121.935,38.335 FL17.2@122.325,38.725
  L3_SIG w0.5: 132.6,11.7 134.7,13.8 J12.10@135,13.8
  L3_SIG w0.8: v1(122,32.5) 129.4,25.1 129.4,13 130.7,11.7 132.6,11.7
USB_DN1_N: J11.2 U24.1 | length 10.7
  TOP w0.11: U24.1@118.2,19.8 118.295,19.705 118.295,17.733 117.19,16.628 117.19,13.772 117.862,13.1 119.1,13.1 119.345,12.855 119.345,12.1 119.225,11.98 J11.2@118.5,11.98
USB_DN1_P: J11.3 U24.2 | length 10.7
  TOP w0.11: U24.2@118.7,19.8 118.605,19.705 118.605,17.605 117.5,16.5 117.5,13.9 117.99,13.41 119.228,13.41 119.655,12.983 119.655,12.1 119.775,11.98 J11.3@120.5,11.98
USB_DN2_N: J11.6 U24.3 | length 10.6
  TOP w0.11: J11.6@118.5,14.6 119.1,14.6 119.295,14.795 119.295,16.001 119.295,16.343 119.579,16.627 121.734,16.627 121.837,16.729 121.837,16.934 121.734,17.037 119.579,17.037 119.295,17.321 119.295,17.595 119.295,19.705 U24.3@119.2,19.8
USB_DN2_P: J11.7 U24.4 | length 10.7
  TOP w0.11: U24.4@119.7,19.8 119.605,19.705 119.605,17.595 119.605,17.449 119.707,17.347 121.862,17.347 122.147,17.063 122.147,16.601 121.862,16.317 119.707,16.317 119.605,16.214 119.605,16.001 119.605,14.795 119.8,14.6 J11.7@120.5,14.6
USB_HSD1_N: U23.6 U24.30 | length 17.5
  TOP w0.11: U23.6@103.6,19.6 103.695,19.695 104.78,19.695 v1(105,19.475) ; v1(115.7,24.6) 115.55,24.6 115.48,24.53 115.48,24.358 116.333,23.505 117.305,23.505 U24.30@117.4,23.6
  BOT w0.11: v1(105,19.475) 105.22,19.695 111.533,19.695 115.48,23.642 115.48,24.38 v1(115.7,24.6)
USB_HSD1_P: U23.7 U24.31 | length 17.5
  TOP w0.11: U23.7@103.6,20.1 103.695,20.005 104.78,20.005 v1(105,20.225) ; v1(114.95,24.6) 115.1,24.6 115.17,24.53 115.17,24.23 116.205,23.195 117.305,23.195 U24.31@117.4,23.1
  BOT w0.11: v1(105,20.225) 105.22,20.005 111.405,20.005 115.17,23.77 115.17,24.38 v1(114.95,24.6)
USB_HSD_N: J9.2 U22.2 U23.8 | length 17.2
  TOP w0.11: J9.2@99.5,12 100.145,12 100.345,12.2 100.345,16.183 100.917,16.755 101.8,16.755 101.9,16.855 ; U22.2@101.9,17.55 101.9,16.855 ; U23.8@103.6,20.6 103.695,20.695 104.595,20.695 104.79,20.89 105.372,20.89 105.89,20.372 105.89,17.628 105.017,16.755 102,16.755 101.9,16.855
USB_HSD_P: J9.3 U22.1 U23.9 | length 17.7
  TOP w0.11: J9.3@101.5,12 100.855,12 100.655,12.2 100.655,16.055 101.045,16.445 101.8,16.445 101.9,16.345 ; U22.1@101.9,15.65 101.9,16.345 ; U23.9@103.6,21.1 103.695,21.005 104.467,21.005 104.662,21.2 105.5,21.2 106.2,20.5 106.2,17.5 105.145,16.445 102,16.445 101.9,16.345
USB_N: J3.103 U23.4 | length 40.9
  TOP w0.11: J3.103@81.4,42.54 81.355,42.585 81.355,43.78 v1(81.575,44) ; v1(89.27,43.6) 89.49,43.38 89.49,37.01 93.09,33.41 93.09,22.372 95.267,20.195 99.105,20.195 U23.4@99.2,20.1
  BOT w0.11: v1(81.575,44) 81.355,43.78 81.355,43.645 81.5,43.5 88.3,43.5 88.8,43 89.362,43 89.49,43.128 89.49,43.38 v1(89.27,43.6)
USB_ON: U21.4 U24.12 | length 21.3
  TOP w0.2: U21.4@107.27,23.85 108.25,23.85 v1(108.3,23.8) ; U24.12@123.1,21.6 v1(124.2,21.6)
  BOT w0.2: v1(108.3,23.8) 109.1,24.6 113.3,24.6 114.2,25.5 117.1,25.5 118.4,24.2 123.1,24.2 123.6,23.7 123.6,22.1 124.1,21.6 v1(124.2,21.6)
USB_OTG_ID: J3.101 R54.1 R55.2 U23.2 | length 36.8
  TOP w0.2: J3.101@81.8,42.54 81.8,42.8 82,43 82.7,43 v1(83.3,42.4) ; v1(97.9,21.2) 98,21.1 U23.2@99.2,21.1
  L3_SIG w0.2: v1(83.3,42.4) 92.2,33.5 v1(92.2,20.5)
  BOT w0.2: v1(92.2,20.5) 92.525,20.175 R55.2@96.6,20.175 ; R54.1@96.6,18.625 R55.2@96.6,20.175 ; v1(97.9,21.2) 96.875,20.175 R55.2@96.6,20.175
USB_P: J3.105 U23.3 | length 41.4
  TOP w0.11: v1(80.825,44) 81.045,43.78 81.045,42.585 J3.105@81,42.54 ; v1(90.02,43.6) 89.8,43.38 89.8,37.138 93.4,33.538 93.4,22.5 95.395,20.505 99.105,20.505 U23.3@99.2,20.6
  BOT w0.11: v1(80.825,44) 81.045,43.78 81.045,43.517 81.372,43.19 88.172,43.19 88.672,42.69 89.49,42.69 89.8,43 89.8,43.38 v1(90.02,43.6)
pads on no net: BT1.0 DC1.1 DC1.5 H1.1 H2.1 H3.1 H4.1 IC1.1 IC1.4 J1.3 J2.5 J2.6 J2.7 J2.8 J3. J3.16 J3.18 J3.19 J3.57 J3.61 J3.62 J3.63 J3.64 J3.67 J3.68 J3.69 J3.70 J3.72 J3.73 J3.75 J3.76 J3.88 J3.89 J3.90 J3.91 J3.94 J3.96 J3.97 J3.102 J3.104 J3.106 J3.111 J3.115 J3.117 J3.121 J3.123 J3.127 J3.128 J3.129 J3.130 J3.133 J3.134 J3.135 J3.136 J3.139 J3.140 J3.141 J3.142 J3.143 J3.145 J3.146 J3.147 J3.148 J3.149 J3.152 J3.154 J3.157 J3.158 J3.159 J3.160 J3.163 J3.164 J3.165 J3.166 J3.169 J3.171 J3.193 J3.194 J3.195 J3.196 J4.8 J6.16 J6.17 J6.18 J6.19 J6.20 J6.21 J6.22 J6.23 J6.24 J6.25 J6.26 J6.27 J6.28 J6.29 J6.30 J7.14 J8.5 J10. U1.2 U1.11 U1.15 U2.1 U3.1 U4.1 U5.7 U5.8 U6.3 U11.7 U11.8 U15.10 U15.46 U15.48 U18.3 U18.4 U18.8 U18.9 U20.3 U20.4 U20.8 U20.9 U24.6 U24.7 U24.8 U24.9 U24.11 U24.14 U24.16 U24.18 U24.19 U24.20 U24.21 U24.34

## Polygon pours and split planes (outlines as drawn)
DGND on L2_GND "NONET_L-01_P-001" (solid, remove dead copper, pour order 25): 48.4,22.4 51.8,25.8 52.6,26.6 55.2,26.6 56.2,27.6 56.2,33.6 53.6,36.2 47.2,36.2 44.2,33.2 44.2,29 43.8,28.6 28.8,28.6 26,25.8 1.4,25.8 0.8,26.4 0.8,81 1.8,82 5.8,82 8,84.2 8,87.6 9.6,89.2 161.2,89.2 162,88.4 162,84.2 164.2,82 168.6,82 169.2,81.4 169.2,75.2 168.6,74.6 135.2,74.6 134,73.4 134,55.4 135.4,54 148,54 151.2,50.8 151.2,1.6 150.4,0.8 49.2,0.8 48.4,1.6
GND on L2_GND "NONET_L-01_P-001" (solid, remove dead copper, pour order 1): 153,24 152.2,24.8 152.2,65.2 154,67 168.2,67 169.2,66 169.2,24.4 168.8,24
GND_ISO on L2_GND "NONET_L-01_P-001" (solid, remove dead copper, pour order 0): 47.6,22.4 52.4,27.2 55.2,27.2 55.6,27.6 55.6,33.6 53.8,35.4 47.4,35.4 44.8,32.8 44.8,28 44.2,27.4 28.8,27.4 26,24.6 1,24.6 0.8,24.4 0.8,9 1.8,8 5.8,8 8,5.8 8,1.6 8.8,0.8 46.8,0.8 47.6,1.6
DGND on TOP "NONET_L-01_P-001" (solid, remove dead copper, pour order 24): 48.4,22.4 51.8,25.8 52.6,26.6 55.2,26.6 56.2,27.6 56.2,33.6 53.6,36.2 47.2,36.2 44.2,33.2 44.2,29 43.8,28.6 28.8,28.6 26,25.8 1.4,25.8 0.8,26.4 0.8,81 1.8,82 5.8,82 8,84.2 8,87.6 9.6,89.2 161.2,89.2 162,88.4 162,84.2 164.2,82 168.6,82 169.2,81.4 169.2,75.2 168.6,74.6 135.2,74.6 134,73.4 134,55.4 135.4,54 148,54 151.2,50.8 151.2,1.6 150.4,0.8 49.2,0.8 48.4,1.6
GND_ISO on TOP "NONET_L-01_P-001" (solid, remove dead copper, pour order 23): 47.6,22.4 52.4,27.2 55.2,27.2 55.6,27.6 55.6,33.6 53.8,35.4 47.4,35.4 44.8,32.8 44.8,28 44.2,27.4 28.8,27.4 26,24.6 1,24.6 0.8,24.4 0.8,9 1.8,8 5.8,8 8,5.8 8,1.6 8.8,0.8 46.8,0.8 47.6,1.6
5V_USB on L4_VCC "NONET_L-01_P-001" (solid, remove dead copper, pour order 2): 94.8,30.6 97.6,30.6 99.8,28.4 106.6,28.4 117.6,17.4 117.6,9.8 117,9.2 93.6,9.2 92,10.8 92,27.8
3V3 on L4_VCC "L4_VCC-3V3" (solid, remove dead copper, pour order 14): 107,29 60.8,29 53.6,36.2 47.2,36.2 44.2,33.2 44.2,29 43.8,28.6 28.8,28.6 26,25.8 1.4,25.8 0.8,26.4 0.8,57 1.2,57.4 9.2,57.4 10.2,58.4 10.2,65.6 11.6,67 55.2,67 61.5,73.3 62.4,74.2 73.6,74.2 80.4,81 82.4,83 131.4,83 132,82.4 132,78.4 131.2,77.6 115.8,77.6 111.4,73.2 111.4,47.4 112.2,46.6 141.4,46.6 149.4,38.6 149.4,2.2 148,0.8 119.8,0.8 118.4,2.2 118.4,17.6
5V on L4_VCC "L4_VCC-5V" (solid, remove dead copper, pour order 13): 54.8,67.8 11.4,67.8 9.6,66 9.6,59 8.6,58 1.4,58 0.8,58.6 0.8,81 1.8,82 5.8,82 8,84.2 8,87.6 9.6,89.2 142.8,89.2 144,88 144,75.2 143.4,74.6 135.2,74.6 134,73.4 134,51.8 135.6,50.2 147,50.2 149.4,47.8 149.4,42.2 149,41.8 147,41.8 141.6,47.2 112.6,47.2 112,47.8 112,73 116,77 131.8,77 132.6,77.8 132.6,82.8 131.8,83.6 82,83.6 79.2,80.8 73.4,75 62,75
24V on L4_VCC "NONET_L-01_P-001" (solid, remove dead copper, pour order 12): 152.2,39.4 161,48.2 165.4,48.2 166.2,47.4 166.2,29.4 164.4,27.6 153,27.6 152.2,28.4
5V_ISO on L4_VCC "NONET_L-01_P-001" (solid, remove dead copper, pour order 6): 28.8,27.4 26,24.6 1,24.6 0.8,24.4 0.8,9 1.8,8 5.8,8 8,5.8 8,1.6 8.8,0.8 46.8,0.8 47.6,1.6 47.6,22.4 51,25.8 52.4,27.2 52.4,35 52,35.4 47.4,35.4 44.8,32.8 44.8,28 44.2,27.4
GND_ISO on L3_SIG "NONET_L-01_P-001" (solid, remove dead copper, pour order 30): 47.6,22.4 52.4,27.2 55.2,27.2 55.6,27.6 55.6,33.6 53.8,35.4 47.4,35.4 44.8,32.8 44.8,28 44.2,27.4 28.8,27.4 26,24.6 1,24.6 0.8,24.4 0.8,9 1.8,8 5.8,8 8,5.8 8,1.6 8.8,0.8 46.8,0.8 47.6,1.6
DGND on L3_SIG "NONET_L-01_P-001" (solid, remove dead copper, pour order 26): 48.4,22.4 52,26 52.6,26.6 55.2,26.6 56.2,27.6 56.2,33.6 53.6,36.2 47.2,36.2 44.2,33.2 44.2,29 43.8,28.6 28.8,28.6 26,25.8 1.4,25.8 0.8,26.4 0.8,81 1.8,82 5.8,82 8,84.2 8,87.6 9.6,89.2 161.2,89.2 162,88.4 162,84.2 164.2,82 168.6,82 169.2,81.4 169.2,75.2 168.6,74.6 135.2,74.6 134,73.4 134,55.4 135.4,54 148,54 151.2,50.8 151.2,1.6 150.4,0.8 49.2,0.8 48.4,1.6
1V05 on L3_SIG "NONET_L-01_P-001" (solid, remove dead copper, pour order 16): 143.6,23 148.4,27.8 148.4,35.2 148.2,35.4 147,35.4 146.6,35 146.6,33.2 138.2,24.8 135.4,24.8 134.8,25.4 134.8,26.6 135.8,27.6 135.8,31 138.4,33.6 138.4,34 138.2,34.2 135.8,34.2 134,32.4 134,29.8 132,27.8 132,24 133,23
GND_ISO on L5_GND "NONET_L-01_P-001" (solid, remove dead copper, pour order 29): 47.6,22.4 52.4,27.2 55.2,27.2 55.6,27.6 55.6,33.6 53.8,35.4 47.4,35.4 44.8,32.8 44.8,28 44.2,27.4 28.8,27.4 26,24.6 1,24.6 0.8,24.4 0.8,9 1.8,8 5.8,8 8,5.8 8,1.6 8.8,0.8 46.8,0.8 47.6,1.6
DGND on L5_GND "NONET_L-01_P-001" (solid, remove dead copper, pour order 27): 48.4,22.4 51.8,25.8 52.6,26.6 55.2,26.6 56.2,27.6 56.2,33.6 53.6,36.2 47.2,36.2 44.2,33.2 44.2,29 43.8,28.6 28.8,28.6 26,25.8 1.4,25.8 0.8,26.4 0.8,81 1.8,82 5.8,82 8,84.2 8,87.6 9.6,89.2 161.2,89.2 162,88.4 162,84.2 164.2,82 168.6,82 169.2,81.4 169.2,75.2 168.6,74.6 135.2,74.6 134,73.4 134,55.4 135.4,54 148,54 151.2,50.8 151.2,1.6 150.4,0.8 49.2,0.8 48.4,1.6
DGND on BOT "NONET_L-01_P-001" (solid, remove dead copper, pour order 28): 48.4,22.4 51.8,25.8 52.6,26.6 55.2,26.6 56.2,27.6 56.2,33.6 53.6,36.2 47.2,36.2 44.2,33.2 44.2,29 43.8,28.6 28.8,28.6 26,25.8 1.4,25.8 0.8,26.4 0.8,81 1.8,82 5.8,82 8,84.2 8,87.6 9.6,89.2 161.2,89.2 162,88.4 162,84.2 164.2,82 168.6,82 169.2,81.4 169.2,75.2 168.6,74.6 135.2,74.6 134,73.4 134,55.4 135.4,54 148,54 151.2,50.8 151.2,1.6 150.4,0.8 49.2,0.8 48.4,1.6
GND_ISO on BOT "NONET_L-01_P-001" (solid, remove dead copper, pour order 21): 47.6,22.4 52.4,27.2 55.2,27.2 55.6,27.6 55.6,33.6 53.8,35.4 47.4,35.4 44.8,32.8 44.8,28 44.2,27.4 28.8,27.4 26,24.6 1,24.6 0.8,24.4 0.8,9 1.8,8 5.8,8 8,5.8 8,1.6 8.8,0.8 46.8,0.8 47.6,1.6

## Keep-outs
Keep-Out Layer:
  lines w0.1: 0,1 ccw(c1,1) 1,0 169,0 ccw(c169,1) 170,1 170,89 ccw(c169,89) 169,90 1,90 ccw(c1,89) 0,89 0,1
  text "Board" at 62.282,-15.92 h1.5

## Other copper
TOP:
  region net 5V: 123,49.6 122.8,49.8 121.5,49.8 121.3,49.6 121.3,46.5 121.6,46.2 122.7,46.2 123,46.5
  region net 5V: 114.4,47.8 116.1,46.1 117.3,46.1 117.6,46.4 117.6,49.6 117.4,49.8 113,49.8 112.6,49.4 112.6,47.9 112.7,47.8 114.4,47.8
  region net 5V_USB: 97.3,31.7 96.7,31.1 96.7,25.7 97.2,25.2 98.8,25.2 98.9,25.3 98.9,31.5 98.7,31.7
  pour cut-out: 79.4,77.6 80.5,78.7 83.6,78.7 85.3,77 85.3,50.4 88.5,47.2 88.5,25.5 86.2,23.2 75.6,23.2 74,24.8 74,31.3 78.1,31.3 84,37.2 84,43.7 77.6,50.1 77.6,54.6 76.3,55.9 76.3,63.6 79.4,66.7 79.4,67.8
  pour cut-out: 53.7,30.1 57.2,30.1 57.5,29.8 57.8,29.8 57.8,32.05 57.5,32.35 55.1,32.35 54.1,31.35
  region net DGND: 127.8,73 127.4,72.6 127.4,68.6 127.8,68.2 129.8,68.2 130,68.4 130,72.8 129.8,73
  region net 5V: 56.6,20.6 56.6,22.2 57,22.6 57,23.3 56.8,23.5 55.3,23.5 54.8,23 54.8,19.8 55,19.6 55.6,19.6
  region net 5V: 133.4,65.3 133.7,65 133.7,59.6 133.4,59.3 131.3,59.3 131.1,59.5 131.1,61.4 131.5,61.8 131.5,65 131.8,65.3
  region net NetC26_1: 132.4,73.5 131.4,72.5 131.4,66.4 131.7,66.1 133.3,66.1 137.8,70.6 137.8,72.8 137.1,73.5
  region net 3V3: 134.4,46.1 134.2,45.9 134.2,43.1 136.3,43.1 136.6,43.4 136.6,45.7 136.6,45.8 136.3,46.1
  region net 3V3: 106.2,36 106,35.8 106,32.9 106.2,32.7 109.4,32.7 109.6,32.9 109.6,35.9 109.5,36
  region net GND: 158.5,24.2 156.8,22.5 156.8,21.5 156.9,21.4 164.5,21.4 165.2,22.1 165.2,26 165,26.2 163.5,26.2 162.9,26.8 159.2,26.8 158.5,26.1
  region net GND: 161.9,62.5 157.5,62.5 155.3,60.3 155.3,57.3 160.4,52.2 161.8,52.2 162.1,52.5 162.1,62.3
  region net NetC1_1: 162.8,50.4 162.9,50.3 165.3,50.3 165.5,50.5 165.5,65.5 164.5,66.5 155.6,66.5 155,65.9 155,63.6 155.6,63 162.4,63 162.8,62.6 162.8,54
  region net 24V: 158.4,27.6 160.4,27.6 160.6,27.8 160.6,33.8 166.2,39.4 166.2,48.4 165.2,49.4 162.2,49.4 152.2,39.4 152.2,32.4 152.6,32 157.4,32 158,31.4 158,28
  region net NetFL1_3: 158,24.5 156.2,22.7 156.2,21.6 156,21.4 153,21.4 152.2,22.2 152.2,26.6 152.6,27 157.8,27 158,26.8
  region net NetFL1_1: 157,19.4 156.8,19.2 156.8,15.8 157.2,15.4 160.2,15.4 160.4,15.6 160.4,19 160,19.4
  region net NetFL1_4: 153,19.4 152.4,18.8 152.4,15.8 152.8,15.4 155.6,15.4 156,15.8 156,19.2 155.8,19.4
  region net NetJ1_2: 158,13.8 157.4,13.2 157.4,7.4 157.8,7 161,7 161.4,7.4 161.4,13.2 160.8,13.8
  region net NetJ1_1: 152.8,13.8 151,12 151,8 152,7 155.2,7 155.4,7.2 155.4,13.4 155,13.8
  region net DGND: 148.6,40.4 148.8,40.4 151.01,40.4 151.11,40.5 151.11,41.8 150.91,42 149,42 148.6,41.6
  region net DGND: 151,37 151.2,36.8 151.2,35.5 151.1,35.4 148.8,35.4 148.6,35.6 148.6,36.8 148.8,37
  region net 1V05: 146.7,37.1 146.7,37.7 147.1,38.1 147.4,38.1 147.9,37.6 147.9,35.4 148.1,35.2 148.2,35.1 148.2,34.3 147.9,34 147,34 146.7,34.3 146.7,34.7
  region net 5V: 147.8,41.6 148.1,41.9 148.1,43.1 147.9,43.3 146.9,43.3 146.6,43 146.6,41 147.3,40.3 147.5,40.3 147.8,40.6
  region net NetC12_1: 108.4,49.2 108.2,49 108.2,47 108.4,46.8 110,46.8 111.4,48.2 111.4,49 111.2,49.2
  region net NetC14_1: 108.4,38.8 108.2,38.6 108.2,37.2 108.6,36.8 109.6,36.8 111.2,35.2 114.2,35.2 114.4,35.4 114.4,36.8 114,37.2 112.2,37.2 110.6,38.8
  region net GND_ISO: 47.5,35.5 47.1,35.1 47.1,33 47.4,32.7 48.8,32.7 48.9,32.8 48.9,35.3 48.7,35.5
  region net GND_ISO: 54,27.8 54.8,28.6 56.9,28.6 57.3,29 57.3,29.9 57.1,30.1 52.3,30.1 51.8,29.6 51.8,28.2 52.2,27.8
  region net 5V_ISO: 49.7,35.5 49.6,35.4 49.6,33.5 49.8,33.3 52.1,33.3 52.4,33.6 52.4,35.3 52.2,35.5
  region net NetC18_2: 52.9,25.3 52.3,25.9 52.3,26.5 52.9,27.1 54.6,27.1 55.2,27.7 56.5,27.7 56.6,27.6 56.7,27.5 56.7,26.4 57,26.1 57,24.7 56.9,24.6 55.3,24.6 54.6,25.3
  region net NetC15_1: 54,30.6 52.7,30.6 52.3,31 52.3,32.5 53.6,33.8 53.6,35.3 53.9,35.6 56.4,35.6 57.3,34.7 57.3,32 57.1,31.8 55.2,31.8
  text "1.TOP" at 62.1,-16.25 h1.5
L3_SIG:
  region net 5V: 107.7,28.4 107.5,28.2 107.5,27.1 107.6,27 108.4,27 109.2,27.8 109.2,28.4
  region net 3V3: 106.6,30 106.2,30 106.2,33.2 106.6,33.6 109.2,33.6 109.4,33.4 109.4,32.8
  region net 5V: 115,49.8 112.6,49.8 111.8,49 111.8,47.6 112.6,47.6 113,48 115,48 115.2,48.2 115.2,49.6
BOT:
  region net 5V: 50.9,20.8 52.6,20.8 52.7,20.7 54.6,20.7 54.8,20.9 54.8,22.2 55,22.4 55.5,22.4 56.2,21.7 56.2,20 55.3,19.1 52.7,19.1 52.3,19.5 50.9,19.5 50.8,19.6 50.8,20.7
  region net 5V: 107.5,28.3 108.1,28.3 108.4,28 108.4,27.1 108.2,26.9 106.9,26.9 106.6,27.2 106.6,27.4
  region net GND: 161.9,62.5 162.1,62.3 162.1,52.5 161.8,52.2 160.4,52.2 155.3,57.3 155.3,60.3 157.5,62.5 158.7,62.5
  region net NetC1_1: 165.3,50.3 165.5,50.5 165.5,65.5 164.5,66.5 155.6,66.5 155,65.9 155,63.6 155.6,63 162.4,63 162.8,62.6 162.8,50.4 162.9,50.3
  text "6.BOTTOM" at 62.1,-16.25 h1.5

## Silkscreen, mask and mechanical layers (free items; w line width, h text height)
Top Overlay:
  drawing of 31 lines, arcs and shapes, not listed
  text "GPIO" at 82.2,88.8 h0.8
  text "5V" at 77.2,87.8 h0.8
  text "3" at 80.2,87.8 h0.8
  text "2" at 82.8,87.8 h0.8
  text "1" at 85.2,87.8 h0.8
  text "0" at 86.8,87.8 h0.8
  text ".Model" at 136.2,82 h1.5
  text "16" at 82.672,81.228 h0.8
  text "7" at 85.272,81.228 h0.8
  text "DGND" at 77,81.2 h0.8
  text "6" at 87.8,81.2 h0.8
  text "GPIO" at 85,80.2 h0.8
  text "9-10 Wake up from Power Down" at 40.8,71.4 h0.8 r270
  text "3-4 EEPROM Write Protection" at 42.2,71.4 h0.8 r270
  text "1-2 Disable eMMC Boot" at 43.6,71.4 h0.8 r270
  text "485B_-" at 0,-2 h0.8
  text "TOP SILK" at 62.9,-15.85 h1.5
Bottom Overlay:
  text "BOTTOM SILK" at 62.3,-15.95 h1.5
Top Paste:
  text "TOP Paste" at 62.032,-15.92 h1.5
Bottom Paste:
  text "BOTTOM Paste" at 62.8,-15.85 h1.5
Top Solder:
  text "TOP Solder" at 62.032,-15.92 h1.5
Bottom Solder:
  text "BOTTOM Solder" at 62.8,-15.85 h1.5
Mechanical 16:
  lines w0.1: 30.1,-17.75 30.1,-7.75 ; 30.1,-12.75 100.1,-12.75 ; 60.1,-17.75 60.1,-7.75 ; 85.1,-17.75 85.1,-7.75 ; 0.1,-17.75 100.1,-17.75 100.1,-7.75 0.1,-7.75 0.1,-17.75
  text "MODEL NAME" at 34.5,-11.95 h2
  text "LAYER NAME" at 62.3,-12.15 h2
  text "DATE" at 89.1,-12.15 h2
  text "NEXTSQUARE" at 2.2,-14.2 h3
  text ".model" at 31.6,-16 h1.2
  text ".Print_Date" at 86.1,-16.25 h1.2
Drill Drawing:
  text "Drill Imformation" at 62.8,-15.95 h1.5

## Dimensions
0,90 to 0,0 on Mechanical 16
0,90 to 170,90 on Mechanical 16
